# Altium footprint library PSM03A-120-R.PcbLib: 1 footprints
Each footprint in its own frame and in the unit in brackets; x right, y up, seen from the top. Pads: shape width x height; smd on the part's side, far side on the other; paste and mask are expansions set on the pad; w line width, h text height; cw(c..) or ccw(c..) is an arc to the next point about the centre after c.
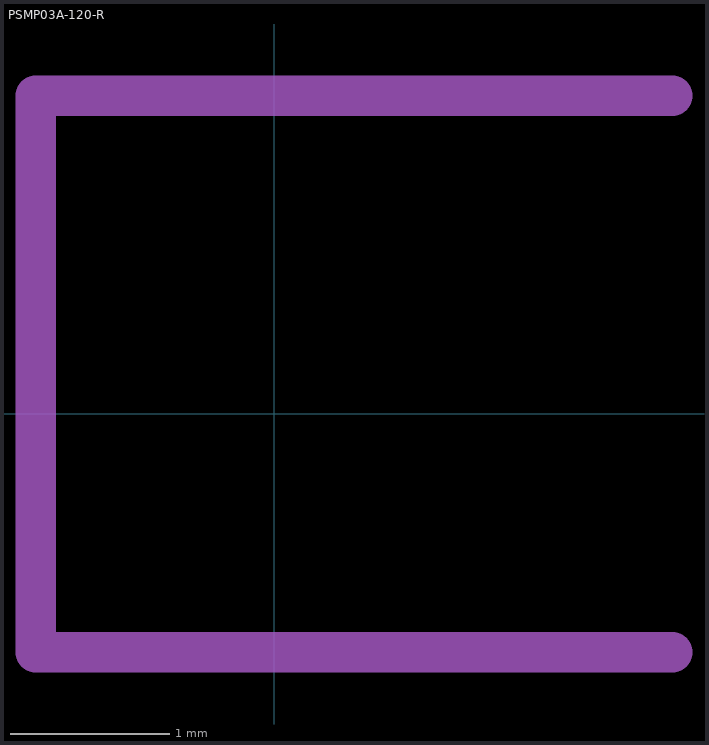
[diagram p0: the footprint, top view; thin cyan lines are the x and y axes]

## PSMP03A-120-R [mm] "PHIHONG WALL WART 12V 230MA"
height 40
M5 Assembly Top:
  lines w0.254: 2.5,-1.5 -1.5,-1.5 -1.5,2 2.5,2
  text ".Designator" at 0,-0.1 h1.02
